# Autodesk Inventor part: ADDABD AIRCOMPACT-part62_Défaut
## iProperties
Shininess: 64.0
Length Units: 11269
Angle Units: 11279
Time Units: 11290
Mass Units: 11283
Length Display Precision: 3
Angle Display Precision: 2
Compacted: True
Part Number: ADDABD AIRCOMPACT-part62_Défaut
Document SubType Name: Modeling
Created: 2006-01
Material: Par défaut
Designer: riri
Density: 0.0
Volumn: 0.0
Area: 0.0
PropertySet Name: Model Information
Control State: 0
Master: False
Checked Out: False
Author: riri
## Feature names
1. Base1
